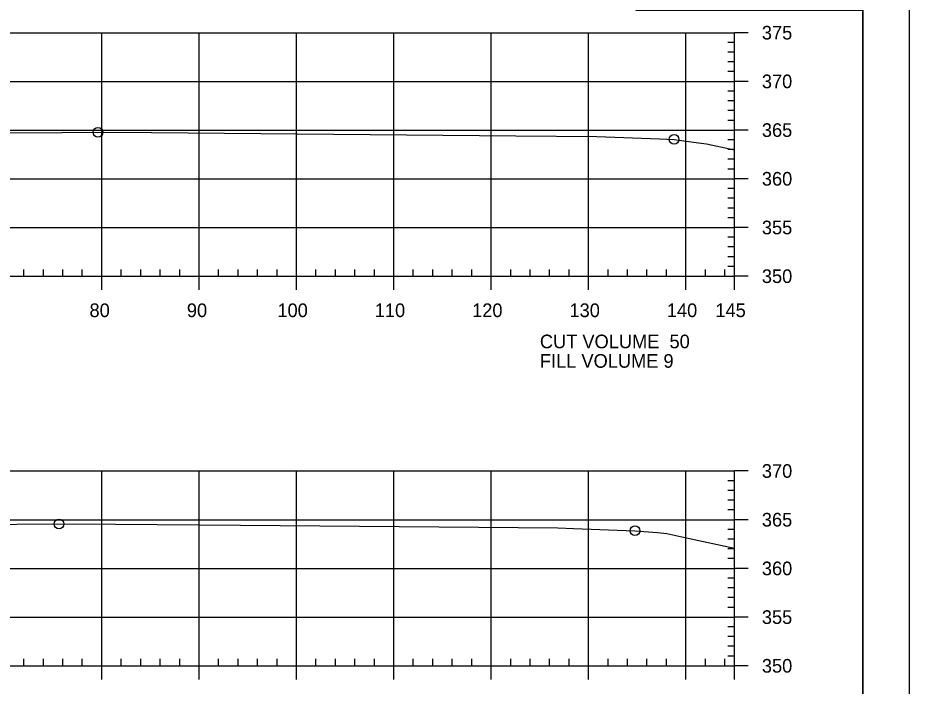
# Model space of a CAD drawing. Extents: x 1359801 to 1362404, y 372415 to 374228.
# Drawn here: x 1361891.3 to 1361982.8, y 373477.5 to 373546.1 of the extents above; entities that cross this region are included whole.
import ezdxf

# ---------------------------------------------------------------- set-up
doc = ezdxf.new("R2010")
doc.units = 0
for name, color, linetype in [('S_DRG_PT_SYM', 7, 'Continuous'), ('S_MAILBOX', 7, 'Continuous'), ('S_PRIMARY_CTL', 7, 'Continuous'), ('S_SHOULDER', 7, 'Continuous'), ('S_UTL_PT_SYM', 7, 'Continuous'), ('S_WATER_UTILITIES', 7, 'Continuous')]:
    doc.layers.add(name, color=color, linetype=linetype)

msp = doc.modelspace()

# ---------------------------------------------------------------- linework, layer by layer
at = {"layer": 'S_DRG_PT_SYM'}
for points in [[(1361890.301, 373534.31), (1361901.277, 373534.382), (1361942.434, 373534.021), (1361950.735, 373533.953), (1361957.167, 373533.703), (1361958.678, 373533.642), (1361961.169, 373533.304), (1361961.997, 373533.196), (1361964.89, 373532.582)], [(1361873.481, 373494.024), (1361897.028, 373494.166), (1361914.13, 373494.033), (1361946.725, 373493.765), (1361948.356, 373493.705), (1361954.655, 373493.463), (1361956.983, 373493.267), (1361957.919, 373493.188), (1361959.472, 373492.853), (1361964.89, 373491.688)]]:
    msp.add_lwpolyline(points, dxfattribs=at)
at = {"layer": 'S_MAILBOX'}
for p, q in [((1361674.89, 373544.598), (1361964.89, 373544.598)), ((1361899.89, 373519.598), (1361899.89, 373544.598)), ((1361909.89, 373519.598), (1361909.89, 373544.598)), ((1361919.89, 373519.598), (1361919.89, 373544.598)), ((1361929.89, 373519.598), (1361929.89, 373544.598)), ((1361939.89, 373519.598), (1361939.89, 373544.598)), ((1361949.89, 373519.598), (1361949.89, 373544.598)), ((1361959.89, 373519.598), (1361959.89, 373544.598)), ((1361964.89, 373519.598), (1361964.89, 373544.598)), ((1361674.89, 373539.598), (1361964.89, 373539.598)), ((1361674.89, 373534.598), (1361964.89, 373534.598)), ((1361674.89, 373529.598), (1361964.89, 373529.598)), ((1361674.89, 373524.598), (1361964.89, 373524.598)), ((1361674.89, 373519.598), (1361964.89, 373519.598)), ((1361674.89, 373499.598), (1361964.89, 373499.598)), ((1361899.89, 373479.598), (1361899.89, 373499.598)), ((1361909.89, 373479.598), (1361909.89, 373499.598)), ((1361919.89, 373479.598), (1361919.89, 373499.598)), ((1361929.89, 373479.598), (1361929.89, 373499.598)), ((1361939.89, 373479.598), (1361939.89, 373499.598)), ((1361949.89, 373479.598), (1361949.89, 373499.598)), ((1361959.89, 373479.598), (1361959.89, 373499.598)), ((1361964.89, 373479.598), (1361964.89, 373499.598)), ((1361674.89, 373494.598), (1361964.89, 373494.598)), ((1361674.89, 373489.598), (1361964.89, 373489.598)), ((1361674.89, 373484.598), (1361964.89, 373484.598)), ((1361674.89, 373479.598), (1361964.89, 373479.598))]:
    msp.add_line(p, q, dxfattribs=at)
at = {"layer": 'S_SHOULDER'}
for points in [[(1361649.483, 373587.952), (1361982.823, 373587.952), (1361982.823, 373374.615), (1361649.483, 373374.615)], [(1361895.81, 373584.058), (1361895.81, 373574.178), (1361931.542, 373574.178), (1361931.542, 373571.258), (1361954.742, 373571.258), (1361954.742, 373546.925), (1361978.07, 373546.925), (1361978.07, 373378.598), (1361661.89, 373378.598), (1361661.89, 373584.058)]]:
    msp.add_lwpolyline(points, close=True, dxfattribs=at)
for centre in [(1361899.497, 373534.37), (1361958.678, 373533.642), (1361895.495, 373494.157), (1361954.655, 373493.463)]:
    msp.add_circle(centre, 0.5, dxfattribs=at)
at = {"layer": 'S_UTL_PT_SYM'}
msp.add_line((1361978.07, 373378.598), (1361978.07, 373584.058), dxfattribs=at)
at = {"layer": 'S_WATER_UTILITIES'}
for p, q in [((1361964.89, 373519.598), (1361964.89, 373544.598)), ((1361966.29, 373544.598), (1361964.89, 373544.598)), ((1361964.89, 373543.598), (1361964.19, 373543.598)), ((1361964.89, 373542.598), (1361964.19, 373542.598)), ((1361964.89, 373541.598), (1361964.19, 373541.598)), ((1361964.89, 373540.598), (1361964.19, 373540.598)), ((1361966.29, 373539.598), (1361964.89, 373539.598)), ((1361964.89, 373538.598), (1361964.19, 373538.598)), ((1361964.89, 373537.598), (1361964.19, 373537.598)), ((1361964.89, 373536.598), (1361964.19, 373536.598)), ((1361964.89, 373535.598), (1361964.19, 373535.598)), ((1361966.29, 373534.598), (1361964.89, 373534.598)), ((1361964.89, 373533.598), (1361964.19, 373533.598)), ((1361964.89, 373532.598), (1361964.19, 373532.598)), ((1361964.89, 373531.598), (1361964.19, 373531.598)), ((1361964.89, 373530.598), (1361964.19, 373530.598)), ((1361966.29, 373529.598), (1361964.89, 373529.598)), ((1361964.89, 373528.598), (1361964.19, 373528.598)), ((1361964.89, 373527.598), (1361964.19, 373527.598)), ((1361964.89, 373526.598), (1361964.19, 373526.598)), ((1361964.89, 373525.598), (1361964.19, 373525.598)), ((1361966.29, 373524.598), (1361964.89, 373524.598)), ((1361964.89, 373523.598), (1361964.19, 373523.598)), ((1361964.89, 373522.598), (1361964.19, 373522.598)), ((1361964.89, 373521.598), (1361964.19, 373521.598)), ((1361964.89, 373520.598), (1361964.19, 373520.598)), ((1361674.89, 373519.598), (1361964.89, 373519.598)), ((1361891.89, 373519.598), (1361891.89, 373520.298)), ((1361893.89, 373519.598), (1361893.89, 373520.298)), ((1361895.89, 373519.598), (1361895.89, 373520.298)), ((1361897.89, 373519.598), (1361897.89, 373520.298)), ((1361899.89, 373518.198), (1361899.89, 373519.598)), ((1361901.89, 373519.598), (1361901.89, 373520.298)), ((1361903.89, 373519.598), (1361903.89, 373520.298)), ((1361905.89, 373519.598), (1361905.89, 373520.298)), ((1361907.89, 373519.598), (1361907.89, 373520.298)), ((1361909.89, 373518.198), (1361909.89, 373519.598)), ((1361911.89, 373519.598), (1361911.89, 373520.298)), ((1361913.89, 373519.598), (1361913.89, 373520.298)), ((1361915.89, 373519.598), (1361915.89, 373520.298)), ((1361917.89, 373519.598), (1361917.89, 373520.298)), ((1361919.89, 373518.198), (1361919.89, 373519.598)), ((1361921.89, 373519.598), (1361921.89, 373520.298)), ((1361923.89, 373519.598), (1361923.89, 373520.298)), ((1361925.89, 373519.598), (1361925.89, 373520.298)), ((1361927.89, 373519.598), (1361927.89, 373520.298)), ((1361929.89, 373518.198), (1361929.89, 373519.598)), ((1361931.89, 373519.598), (1361931.89, 373520.298)), ((1361933.89, 373519.598), (1361933.89, 373520.298)), ((1361935.89, 373519.598), (1361935.89, 373520.298)), ((1361937.89, 373519.598), (1361937.89, 373520.298)), ((1361939.89, 373518.198), (1361939.89, 373519.598)), ((1361941.89, 373519.598), (1361941.89, 373520.298)), ((1361943.89, 373519.598), (1361943.89, 373520.298)), ((1361945.89, 373519.598), (1361945.89, 373520.298)), ((1361947.89, 373519.598), (1361947.89, 373520.298)), ((1361949.89, 373518.198), (1361949.89, 373519.598)), ((1361951.89, 373519.598), (1361951.89, 373520.298)), ((1361953.89, 373519.598), (1361953.89, 373520.298)), ((1361955.89, 373519.598), (1361955.89, 373520.298)), ((1361957.89, 373519.598), (1361957.89, 373520.298)), ((1361959.89, 373518.198), (1361959.89, 373519.598)), ((1361961.89, 373519.598), (1361961.89, 373520.298)), ((1361963.89, 373519.598), (1361963.89, 373520.298)), ((1361964.89, 373518.198), (1361964.89, 373519.598)), ((1361966.29, 373519.598), (1361964.89, 373519.598)), ((1361964.89, 373479.598), (1361964.89, 373499.598)), ((1361966.29, 373499.598), (1361964.89, 373499.598)), ((1361964.89, 373498.598), (1361964.19, 373498.598)), ((1361964.89, 373497.598), (1361964.19, 373497.598)), ((1361964.89, 373496.598), (1361964.19, 373496.598)), ((1361964.89, 373495.598), (1361964.19, 373495.598)), ((1361966.29, 373494.598), (1361964.89, 373494.598)), ((1361964.89, 373493.598), (1361964.19, 373493.598)), ((1361964.89, 373492.598), (1361964.19, 373492.598)), ((1361964.89, 373491.598), (1361964.19, 373491.598)), ((1361964.89, 373490.598), (1361964.19, 373490.598)), ((1361966.29, 373489.598), (1361964.89, 373489.598)), ((1361964.89, 373488.598), (1361964.19, 373488.598)), ((1361964.89, 373487.598), (1361964.19, 373487.598)), ((1361964.89, 373486.598), (1361964.19, 373486.598)), ((1361964.89, 373485.598), (1361964.19, 373485.598)), ((1361966.29, 373484.598), (1361964.89, 373484.598)), ((1361964.89, 373483.598), (1361964.19, 373483.598)), ((1361964.89, 373482.598), (1361964.19, 373482.598)), ((1361964.89, 373481.598), (1361964.19, 373481.598)), ((1361891.89, 373479.598), (1361891.89, 373480.298)), ((1361893.89, 373479.598), (1361893.89, 373480.298)), ((1361895.89, 373479.598), (1361895.89, 373480.298)), ((1361897.89, 373479.598), (1361897.89, 373480.298)), ((1361901.89, 373479.598), (1361901.89, 373480.298)), ((1361903.89, 373479.598), (1361903.89, 373480.298)), ((1361905.89, 373479.598), (1361905.89, 373480.298)), ((1361907.89, 373479.598), (1361907.89, 373480.298)), ((1361911.89, 373479.598), (1361911.89, 373480.298)), ((1361913.89, 373479.598), (1361913.89, 373480.298)), ((1361915.89, 373479.598), (1361915.89, 373480.298)), ((1361917.89, 373479.598), (1361917.89, 373480.298)), ((1361921.89, 373479.598), (1361921.89, 373480.298)), ((1361923.89, 373479.598), (1361923.89, 373480.298)), ((1361925.89, 373479.598), (1361925.89, 373480.298)), ((1361927.89, 373479.598), (1361927.89, 373480.298)), ((1361931.89, 373479.598), (1361931.89, 373480.298)), ((1361933.89, 373479.598), (1361933.89, 373480.298)), ((1361935.89, 373479.598), (1361935.89, 373480.298)), ((1361937.89, 373479.598), (1361937.89, 373480.298)), ((1361941.89, 373479.598), (1361941.89, 373480.298)), ((1361943.89, 373479.598), (1361943.89, 373480.298)), ((1361945.89, 373479.598), (1361945.89, 373480.298)), ((1361947.89, 373479.598), (1361947.89, 373480.298)), ((1361951.89, 373479.598), (1361951.89, 373480.298)), ((1361953.89, 373479.598), (1361953.89, 373480.298)), ((1361955.89, 373479.598), (1361955.89, 373480.298)), ((1361957.89, 373479.598), (1361957.89, 373480.298)), ((1361961.89, 373479.598), (1361961.89, 373480.298)), ((1361963.89, 373479.598), (1361963.89, 373480.298)), ((1361964.89, 373480.598), (1361964.19, 373480.598)), ((1361674.89, 373479.598), (1361964.89, 373479.598)), ((1361899.89, 373478.198), (1361899.89, 373479.598)), ((1361909.89, 373478.198), (1361909.89, 373479.598)), ((1361919.89, 373478.198), (1361919.89, 373479.598)), ((1361929.89, 373478.198), (1361929.89, 373479.598)), ((1361939.89, 373478.198), (1361939.89, 373479.598)), ((1361949.89, 373478.198), (1361949.89, 373479.598)), ((1361959.89, 373478.198), (1361959.89, 373479.598)), ((1361964.89, 373478.198), (1361964.89, 373479.598)), ((1361966.29, 373479.598), (1361964.89, 373479.598))]:
    msp.add_line(p, q, dxfattribs=at)

# ---------------------------------------------------------------- texts
at = {"layer": 'S_PRIMARY_CTL'}
for s, p in [('375', (1361967.69, 373543.898)), ('370', (1361967.69, 373538.898)), ('365', (1361967.69, 373533.898)), ('360', (1361967.69, 373528.898)), ('355', (1361967.69, 373523.898)), ('350', (1361967.69, 373518.898)), ('80', (1361898.629, 373515.398)), ('90', (1361908.629, 373515.398)), ('100', (1361917.929, 373515.398)), ('110', (1361927.929, 373515.398)), ('120', (1361937.929, 373515.398)), ('130', (1361947.929, 373515.398)), ('140', (1361957.929, 373515.398)), ('145', (1361962.916, 373515.398)), ('CUT VOLUME  50', (1361944.89, 373512.198)), ('FILL VOLUME 9', (1361944.89, 373510.198)), ('370', (1361967.69, 373498.898)), ('365', (1361967.69, 373493.898)), ('360', (1361967.69, 373488.898)), ('355', (1361967.69, 373483.898)), ('350', (1361967.69, 373478.898))]:
    msp.add_text(s, height=1.4, dxfattribs=at).set_placement(p)
at = {"layer": 'S_SHOULDER'}
for p in [(1361950.693, 373533.903), (1361946.682, 373493.715)]:
    msp.add_text('+', height=0.1, dxfattribs=at).set_placement(p)

doc.saveas('drawing.dxf')
